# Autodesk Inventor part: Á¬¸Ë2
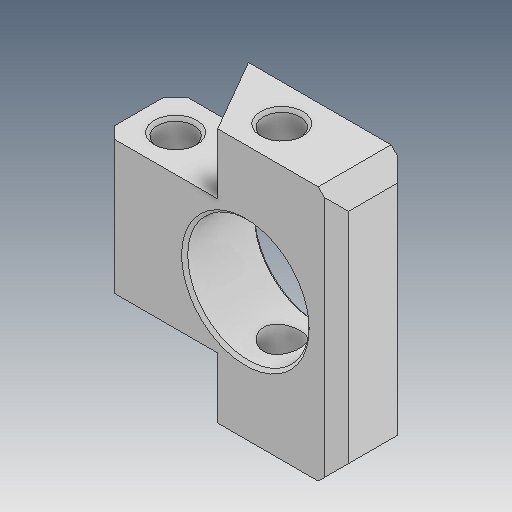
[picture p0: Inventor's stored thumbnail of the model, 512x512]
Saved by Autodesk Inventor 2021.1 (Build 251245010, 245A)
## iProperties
Created: 2014-12
Part Number: Á¬¸Ë2
Material: Ogólny
Document SubType Name: Modeling
Designer: user
Density: 1 g/cm^3
Appearance: Domyślna
Author: user
Revision Number: ÈÎºÎ
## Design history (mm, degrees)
feature "ÊäÈë1"
node "Bryła1"
